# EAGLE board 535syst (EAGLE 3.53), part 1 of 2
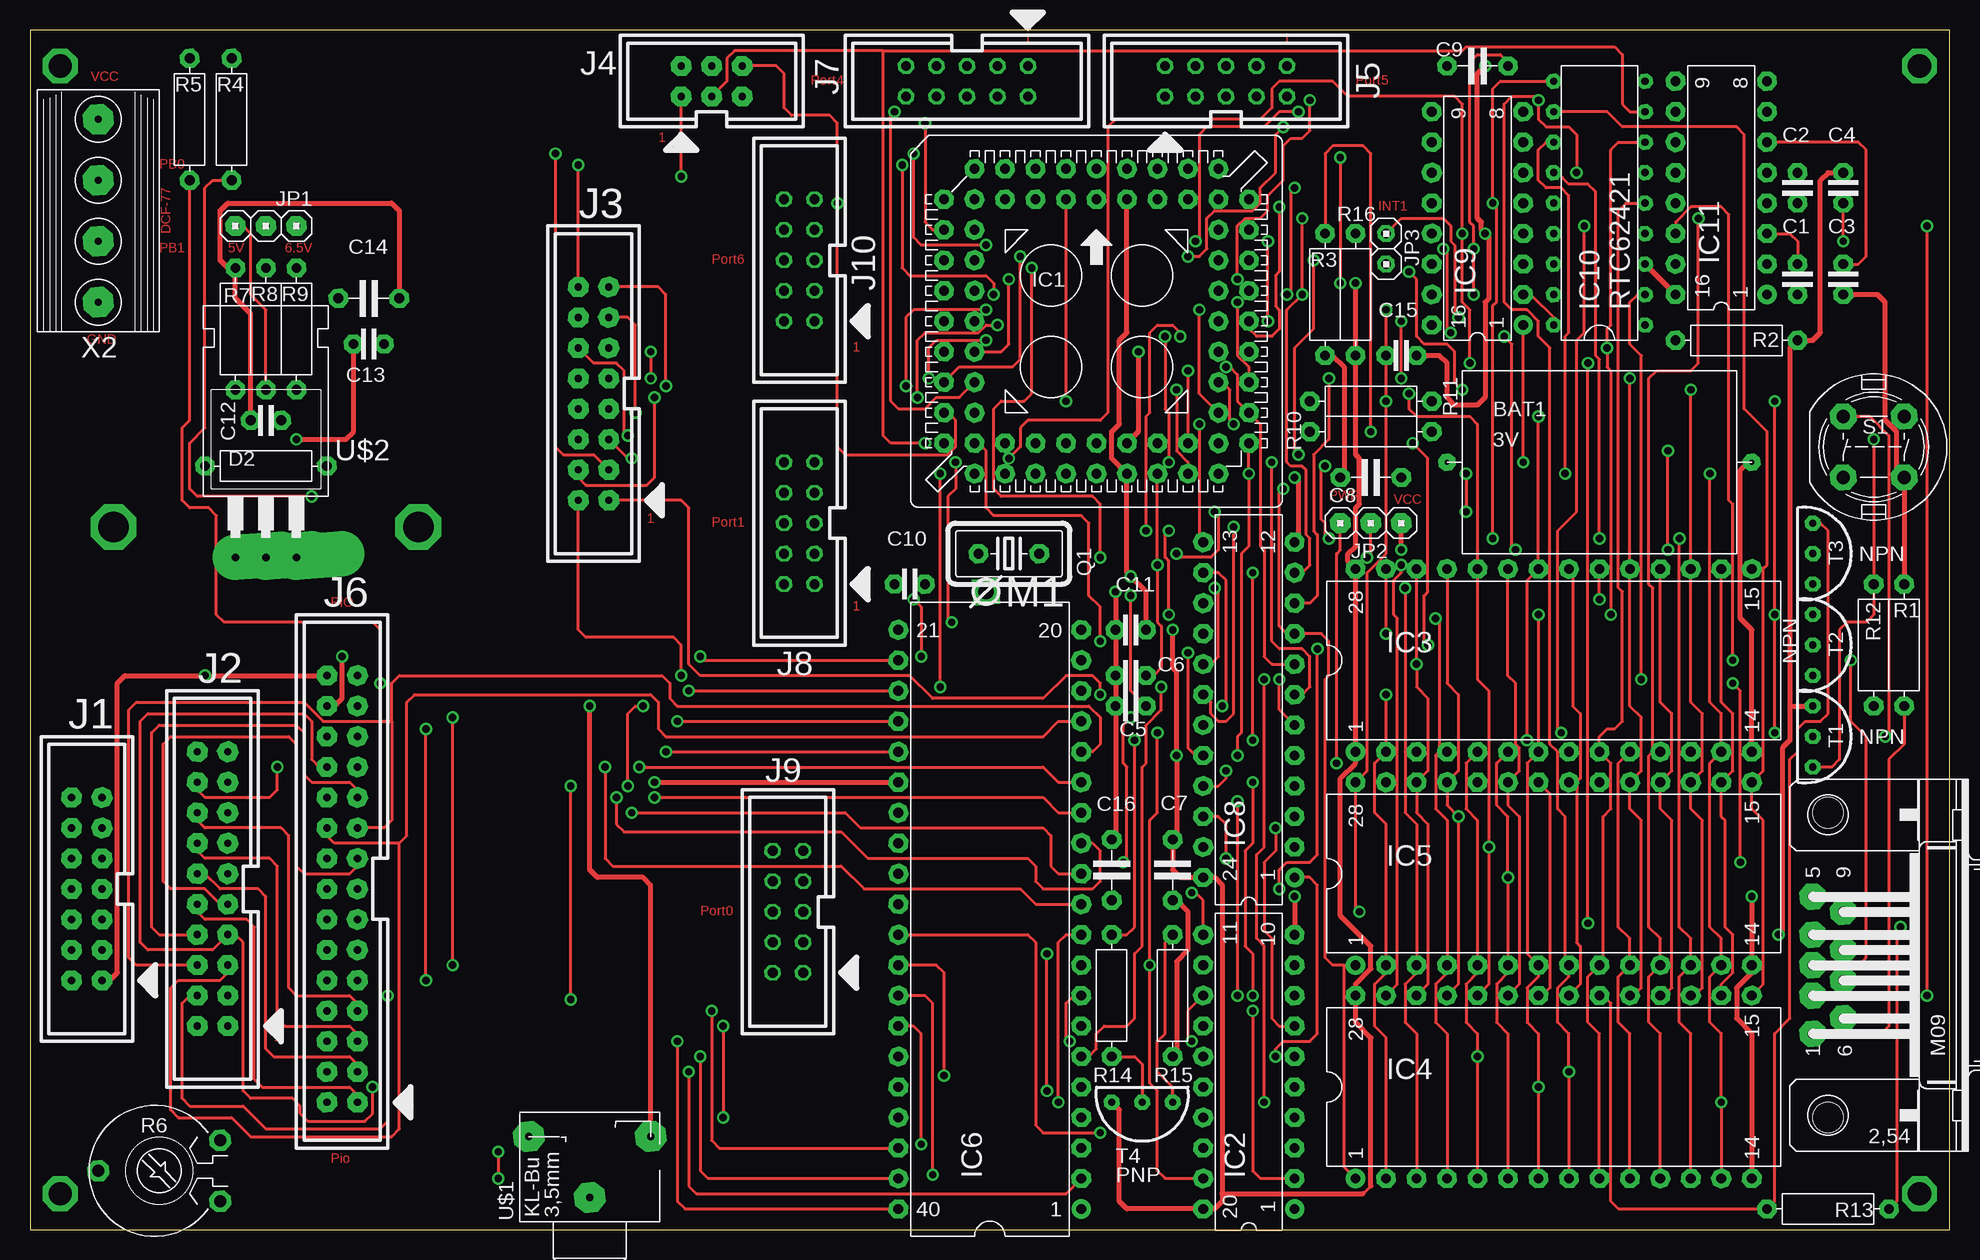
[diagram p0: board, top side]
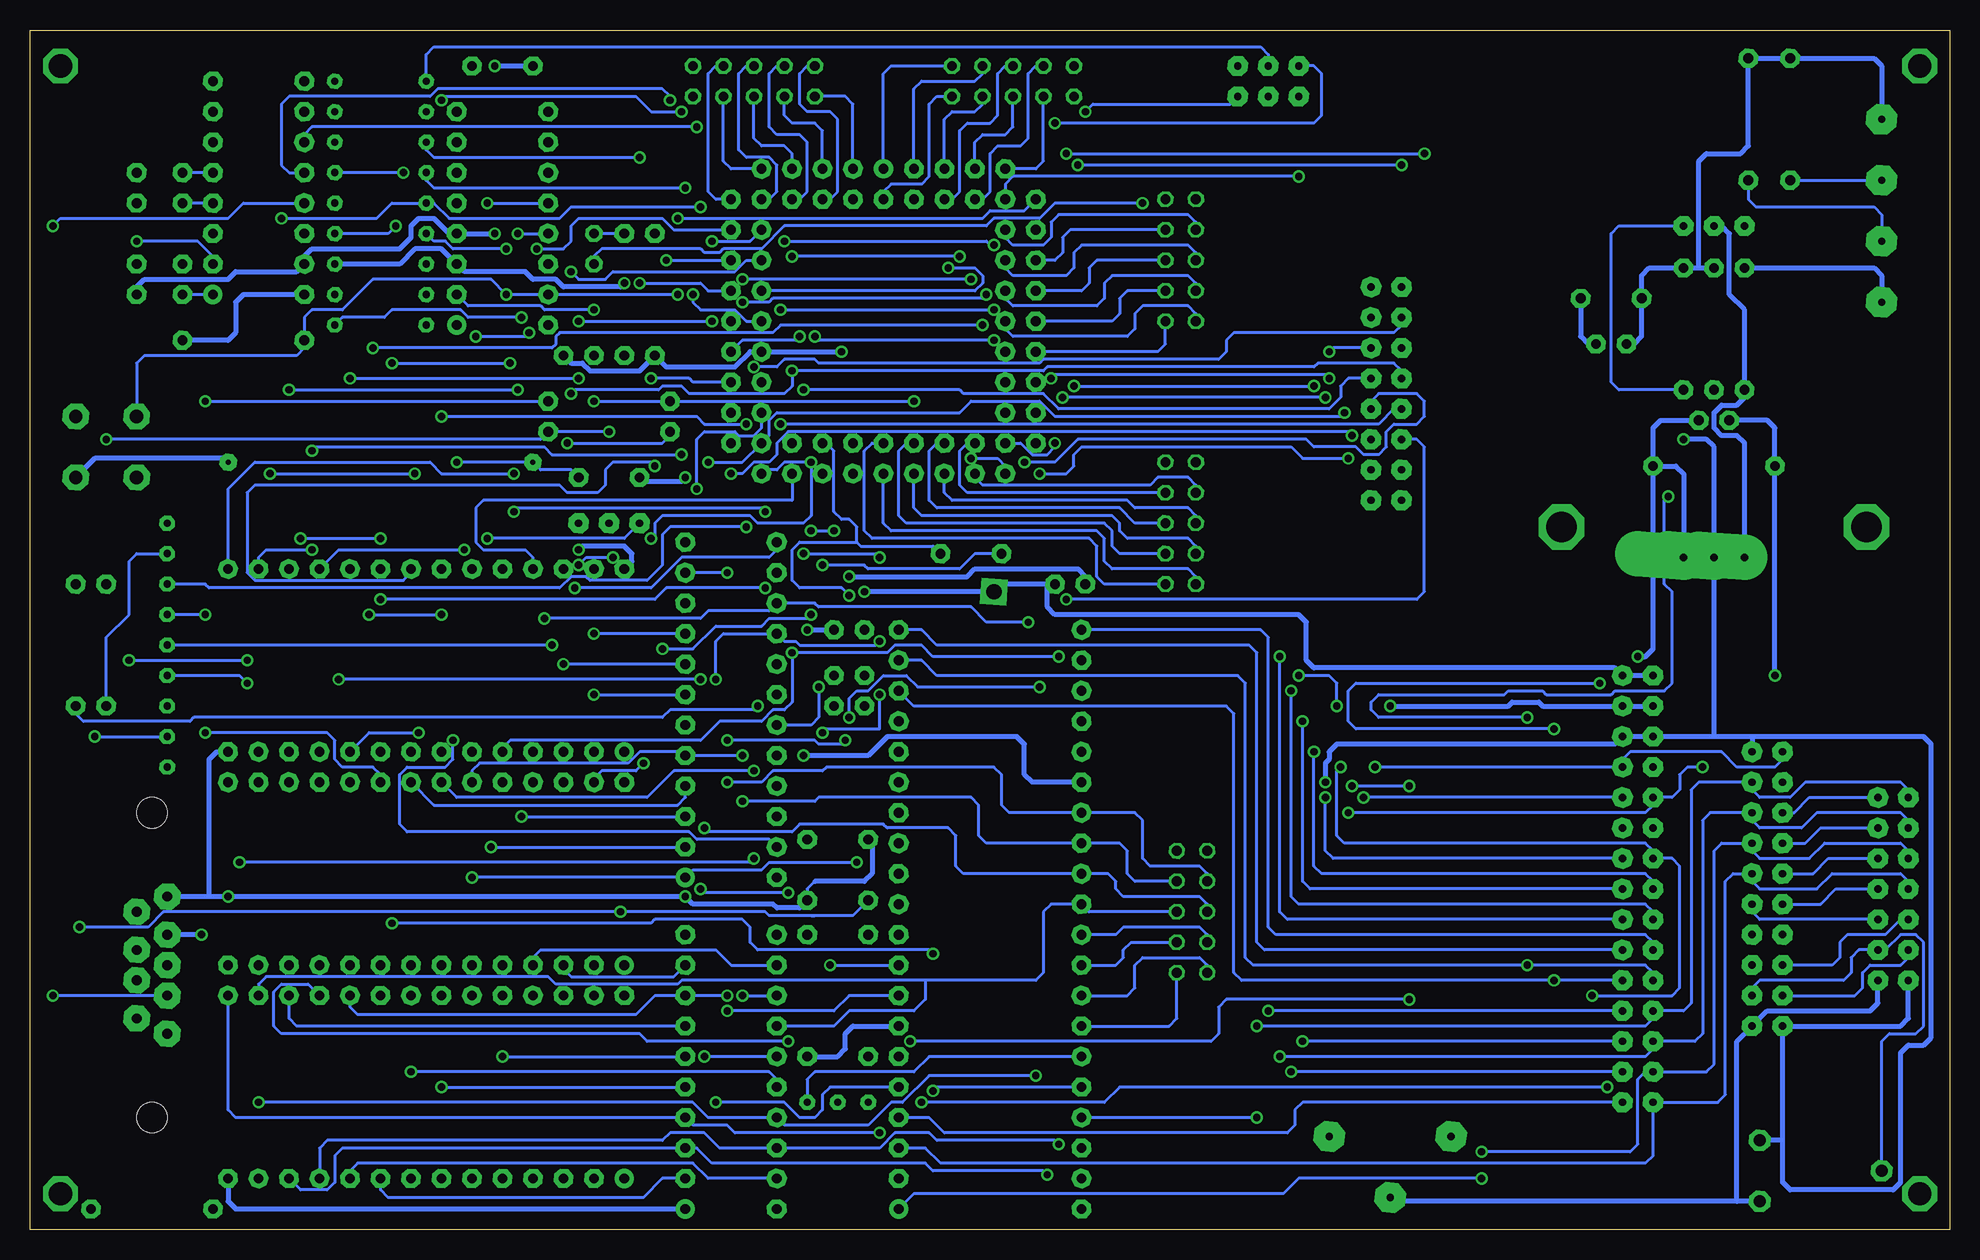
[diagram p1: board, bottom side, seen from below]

Size 159.99 x 99.97 mm. Coordinates in mm from the lower left corner, seen from the top.
Outline: 0,0 159.99,0 159.99,99.97 0,99.97 0,0
Copper layers used: Top, Bottom

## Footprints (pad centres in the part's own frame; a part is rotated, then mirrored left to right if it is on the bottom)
 = drill 0.406 pad 1.422 octagon:  -12.7,0;  12.7,0
2,5 = drill 0.813 pad 1.6 octagon:  -1.27,0;  1.27,0
5 = drill 0.813 pad 1.6 octagon:  -2.54,0;  2.54,0
10 = drill 0.813 pad 1.6 octagon:  -5.08,0;  5.08,0
8 = drill 0.813 pad 1.6 round:  0,12.7 | drill 0.813 pad 1.6 octagon:  0,10.16;  -2.54,12.7;  -2.54,10.16;  -5.08,12.7;  -5.08,10.16;  -7.62,12.7;  -7.62,10.16;  -10.16,12.7;  -12.7,10.16;  -10.16,10.16;  -12.7,7.62;  -10.16,7.62;  -12.7,5.08;  -10.16,5.08;  -12.7,2.54;  -10.16,2.54;  -12.7,0;  -10.16,0;  -12.7,-2.54;  -10.16,-2.54;  -12.7,-5.08;  -10.16,-5.08;  -12.7,-7.62;  -10.16,-7.62;  -12.7,-10.16;  -10.16,-12.7;  -10.16,-10.16;  -7.62,-12.7;  -7.62,-10.16;  -5.08,-12.7;  -5.08,-10.16;  -2.54,-12.7;  -2.54,-10.16;  0,-12.7;  0,-10.16;  2.54,-12.7;  2.54,-10.16;  5.08,-12.7;  5.08,-10.16;  7.62,-12.7;  7.62,-10.16;  10.16,-12.7;  12.7,-10.16;  10.16,-10.16;  12.7,-7.62;  10.16,-7.62;  12.7,-5.08;  10.16,-5.08;  12.7,-2.54;  10.16,-2.54;  12.7,0;  10.16,0;  12.7,2.54;  10.16,2.54;  12.7,5.08;  10.16,5.08;  12.7,7.62;  10.16,7.62;  12.7,10.16;  10.16,12.7;  10.16,10.16;  7.62,12.7;  7.62,10.16;  5.08,12.7;  5.08,10.16;  2.54,12.7;  2.54,10.16
L20 = drill 0.813 pad 1.6 round:  -11.43,-3.81 | drill 0.813 pad 1.6 octagon:  -8.89,-3.81;  -6.35,-3.81;  -3.81,-3.81;  -1.27,-3.81;  1.27,-3.81;  3.81,-3.81;  6.35,-3.81;  8.89,-3.81;  11.43,-3.81;  11.43,3.81;  8.89,3.81;  6.35,3.81;  3.81,3.81;  1.27,3.81;  -1.27,3.81;  -3.81,3.81;  -6.35,3.81;  -8.89,3.81;  -11.43,3.81
L28-6 = drill 0.813 pad 1.6 round:  -16.51,-7.62 | drill 0.813 pad 1.6 octagon:  -13.97,-7.62;  -11.43,-7.62;  -8.89,-7.62;  -6.35,-7.62;  -3.81,-7.62;  -1.27,-7.62;  1.27,-7.62;  3.81,-7.62;  6.35,-7.62;  8.89,-7.62;  11.43,-7.62;  13.97,-7.62;  16.51,-7.62;  16.51,7.62;  13.97,7.62;  11.43,7.62;  8.89,7.62;  6.35,7.62;  3.81,7.62;  1.27,7.62;  -1.27,7.62;  -3.81,7.62;  -6.35,7.62;  -8.89,7.62;  -11.43,7.62;  -13.97,7.62;  -16.51,7.62
L40 = drill 0.813 pad 1.6 round:  -24.13,-7.62 | drill 0.813 pad 1.6 octagon:  -21.59,-7.62;  -19.05,-7.62;  -16.51,-7.62;  -13.97,-7.62;  -11.43,-7.62;  -8.89,-7.62;  -6.35,-7.62;  -3.81,-7.62;  -1.27,-7.62;  1.27,-7.62;  3.81,-7.62;  6.35,-7.62;  8.89,-7.62;  11.43,-7.62;  13.97,-7.62;  16.51,-7.62;  19.05,-7.62;  21.59,-7.62;  24.13,-7.62;  24.13,7.62;  21.59,7.62;  19.05,7.62;  16.51,7.62;  13.97,7.62;  11.43,7.62;  8.89,7.62;  6.35,7.62;  3.81,7.62;  1.27,7.62;  -1.27,7.62;  -3.81,7.62;  -6.35,7.62;  -8.89,7.62;  -11.43,7.62;  -13.97,7.62;  -16.51,7.62;  -19.05,7.62;  -21.59,7.62;  -24.13,7.62
L24-3 = drill 0.813 pad 1.6 round:  -13.97,-3.81 | drill 0.813 pad 1.6 octagon:  -11.43,-3.81;  -8.89,-3.81;  -6.35,-3.81;  -3.81,-3.81;  -1.27,-3.81;  1.27,-3.81;  3.81,-3.81;  6.35,-3.81;  8.89,-3.81;  11.43,-3.81;  13.97,-3.81;  13.97,3.81;  11.43,3.81;  8.89,3.81;  6.35,3.81;  3.81,3.81;  1.27,3.81;  -1.27,3.81;  -3.81,3.81;  -6.35,3.81;  -8.89,3.81;  -11.43,3.81;  -13.97,3.81
L16 = drill 0.813 pad 1.6 round:  -8.89,-3.81 | drill 0.813 pad 1.6 octagon:  -6.35,-3.81;  -3.81,-3.81;  -1.27,-3.81;  1.27,-3.81;  3.81,-3.81;  6.35,-3.81;  8.89,-3.81;  8.89,3.81;  6.35,3.81;  3.81,3.81;  1.27,3.81;  -1.27,3.81;  -3.81,3.81;  -6.35,3.81;  -8.89,3.81
C62421 = drill 0.61 pad 1.27 octagon: 0 10.16,3.81; 1 7.62,3.81; 2 5.08,3.81; 3 2.54,3.81; 4 0,3.81; 5 -2.54,3.81; 6 -5.08,3.81; 7 -7.62,3.81; 8 -10.16,3.81;  -10.16,-3.81;  -7.62,-3.81;  -5.08,-3.81;  -2.54,-3.81;  0,-3.81;  2.54,-3.81;  5.08,-3.81;  7.62,-3.81;  10.16,-3.81
ABA14 = drill 0.61 pad 1.676 octagon:  -7.62,-1.27;  -5.08,-1.27;  -2.54,-1.27;  0,-1.27;  2.54,-1.27;  5.08,-1.27;  7.62,-1.27;  7.62,1.27;  5.08,1.27;  2.54,1.27;  0,1.27;  -2.54,1.27;  -5.08,1.27;  -7.62,1.27
ABA20 = drill 0.61 pad 1.676 octagon:  -11.43,-1.27;  -8.89,-1.27;  -6.35,-1.27;  -3.81,-1.27;  -1.27,-1.27;  -1.27,1.27;  -3.81,1.27;  -6.35,1.27;  -8.89,1.27;  -11.43,1.27;  1.27,1.27;  1.27,-1.27;  3.81,1.27;  3.81,-1.27;  6.35,-1.27;  8.89,-1.27;  11.43,-1.27;  11.43,1.27;  8.89,1.27;  6.35,1.27
ABA16 = drill 0.61 pad 1.676 octagon:  -6.35,-1.27;  -3.81,-1.27;  -1.27,-1.27;  1.27,-1.27;  3.81,-1.27;  6.35,-1.27;  8.89,-1.27;  8.89,1.27;  6.35,1.27;  3.81,1.27;  1.27,1.27;  -1.27,1.27;  -3.81,1.27;  -6.35,1.27;  -8.89,1.27;  -8.89,-1.27
ABA6 = drill 0.61 pad 1.676 octagon:  -2.54,1.27;  0,-1.27;  2.54,-1.27;  2.54,1.27;  0,1.27;  -2.54,-1.27
ABA10 = drill 0.813 pad 1.27 octagon:  -5.08,-1.27;  -2.54,-1.27;  0,-1.27;  2.54,-1.27;  5.08,-1.27;  5.08,1.27;  2.54,1.27;  0,1.27;  -2.54,1.27;  -5.08,1.27
ABA30 = drill 0.61 pad 1.676 octagon:  -17.78,-1.27;  -15.24,-1.27;  -12.7,-1.27;  -10.16,-1.27;  -7.62,-1.27;  -7.62,1.27;  -10.16,1.27;  -12.7,1.27;  -15.24,1.27;  -17.78,1.27;  -5.08,1.27;  -5.08,-1.27;  -2.54,1.27;  -2.54,-1.27;  0,-1.27;  2.54,-1.27;  5.08,-1.27;  5.08,1.27;  2.54,1.27;  0,1.27;  7.62,-1.27;  10.16,-1.27;  12.7,-1.27;  15.24,-1.27;  17.78,-1.27;  17.78,1.27;  15.24,1.27;  12.7,1.27;  10.16,1.27;  7.62,1.27
03 = drill 0.61 pad 1.676 octagon:  -2.54,0;  0,0;  2.54,0
02 = drill 0.813 pad 1.422 octagon:  -1.27,0;  1.27,0
TSTIFT = drill 1.27 pad 2.184 square:  0,0
18U-V = drill 0.813 pad 1.6 octagon:  -2.54,0;  2.54,0
-10 = drill 1.016 pad 1.778 octagon:  -2.54,-5.08;  2.54,-5.08;  0,5.08
6 = drill 1.118 pad 2.159 octagon:  -2.54,2.54;  2.54,2.54;  2.54,-2.54;  -2.54,-2.54
N-PNP = drill 0.61 pad 1.27 octagon:  -2.54,0;  0,0;  2.54,0
INKEN = drill 0.61 pad 2.54 octagon:  -2.54,0;  2.54,-5.08;  2.54,5.08
220H = drill 0.61 pad 3.81 offset:  -2.54,-6.35;  0,-6.35;  2.54,-6.35
NN09 = drill 0.813 pad 2.184 octagon:  -5.715,1.27;  5.715,1.27;  0,1.27;  -2.54,1.27;  2.54,1.27;  -4.445,-1.27;  -1.27,-1.27;  1.27,-1.27;  4.445,-1.27 | hole 2.54: -12.7,0; 12.7,0
AMP-04 = drill 0.61 pad 2.54 octagon:  -7.62,0;  -2.54,0;  2.54,0;  7.62,0

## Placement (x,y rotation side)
BAT1  3V  []  130.78,63.96 0 top
C1  10æ  [2,5]  147.29,79.2 90 top
C2  10æ  [2,5]  147.29,86.82 90 top
C3  10æ  [2,5]  151.1,79.2 90 top
C4  10æ  [2,5]  151.1,86.82 90 top
C5  22p  [2,5]  91.73,43.64 0 top
C6  22p  [2,5]  91.73,46.18 0 top
C7  100nF  [5]  95.22,29.98 270 top
C8  100nF  [5]  111.73,62.69 0 top
C9  100nF  [5]  120.62,96.98 0 top
C10  10æ  [2,5]  73.32,53.8 0 top
C11  680p  [2,5]  91.73,49.99 0 top
C12  10æ  [2,5]  19.66,67.45 180 top
C13  100æ  [2,5]  28.23,73.8 0 top
C14  220n  [5]  28.23,77.61 180 top
C15  10æF  [2,5]  114.27,72.85 0 top
C16  100nF  [5]  90.14,29.98 90 top
D2  1N4007  [10]  19.66,63.64 0 top
IC1  80C535  [8]  88.87,75.7 0 top
IC2  74373  [L20]  101.57,13.16 90 top
IC3  27C256  [L28-6]  126.97,47.45 0 top
IC4  28C256  [L28-6]  126.97,11.89 0 top
IC5  62256  [L28-6]  126.97,29.67 0 top
IC6  82C55A  [L40]  79.98,25.86 90 top
IC8  5C060  [L24-3]  101.57,43.32 90 top
IC9  MAX693  [L16]  120.62,84.28 90 top
IC10  RTC62421  [C62421]  130.78,85.55 90 top
IC11  MAX232  [L16]  140.94,86.82 90 top
J1  FLABA14  [ABA14]  4.74,28.4 270 top
J2  FLABA20  [ABA20]  15.21,28.4 270 top
J3  FLABA16  [ABA16]  46.96,69.67 270 top
J4  FLABA6  [ABA6]  56.81,95.71 180 top
J5  FLABA10  [ABA10]  99.67,95.71 0 top
J6  FLABA30  [ABA30]  26.01,28.4 270 top
J7  FLABA10  [ABA10]  78.08,95.71 180 top
J8  FLABA10  [ABA10]  64.11,58.88 90 top
J9  FLABA10  [ABA10]  63.16,26.49 90 top
J10  FLABA10  [ABA10]  64.11,80.78 90 top
JP1  CON03X1  [03]  19.66,83.64 180 top
JP2  CON03X1  [03]  111.73,58.88 0 top
JP3  CON02X1  [02]  113,81.74 90 top
M1  LTSTIFT  [TSTIFT]  79.67,53.16 0 top
Q1  12MHz  [18U-V]  81.57,56.34 0 top
R1  10k  [10]  156.18,48.72 90 top
R2  1k  [10]  142.21,74.12 0 top
R3  4k7  [10]  107.92,77.93 90 top
R4  10k  [10]  16.8,92.53 90 top
R5  10k  [10]  13.31,92.53 90 top
R6  10k  [-10]  10.77,4.9 90 top
R7  470R  [10]  17.12,75.07 270 top
R8  150R  [10]  19.66,75.07 90 top
R9  100R  [10]  22.2,75.07 90 top
R10  4k7  [10]  111.73,66.5 0 top
R11  10k  [10]  111.73,69.04 0 top
R12  4k7  [10]  153.64,48.72 90 top
R13  10k  [10]  149.83,1.73 180 top
R14  4k7  [10]  90.14,19.51 90 top
R15  1k  [10]  95.22,19.51 90 top
R16  4k7  [10]  110.46,77.93 90 top
S1  DT6  [6]  153.64,65.23 0 top
T1  NPN  [N-PNP]  148.56,41.1 90 top
T2  NPN  [N-PNP]  148.56,48.72 90 top
T3  NPN  [N-PNP]  148.56,56.34 90 top
T4  PNP  [N-PNP]  92.68,10.62 0 top
U$1  KLINKEN  [INKEN]  46.65,5.22 90 top
U$2  LM317  [220H]  19.66,62.37 0 top
X1  9 pol  [NN09]  149.83,22.05 90 top
X2  DCF  [AMP-04]  5.69,84.91 270 top

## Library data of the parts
BAT1 = BATTERY
C1-C16 D2 R1-R16 = DISCRETE
IC1 = INTEL
IC2 = 74XX
IC3 IC4 = MEMNEC
IC5 = MEMHITCH
IC6 = HARRIS
IC8 = PAL
IC9 IC11 = MAXIM
IC10 = Clock
J1-J10 JP1-JP3 M1 X2 = CONNECT
Q1 = QUARTZ
S1 = KEY
T1-T4 U$2 = LINEAR
U$1 = HIRSCHM
X1 = SUBD-A

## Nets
+12V: C12. D2. J6. U$1. U$2.
A0: IC2. IC3. IC4. IC5. IC6. IC10. J3.
A1: IC2. IC3. IC4. IC5. IC6. IC10. J3.
A2: IC2. IC3. IC4. IC5. IC10. J3.
A3: IC2. IC3. IC4. IC5. IC10. J3.
A4: IC2. IC3. IC4. IC5. IC8. J3.
A5: IC2. IC3. IC4. IC5. IC8. J3.
A6: IC2. IC3. IC4. IC5. IC8. J3.
A7: IC2. IC3. IC4. IC5. IC8. J3.
A8: IC1. IC3. IC4. IC5. IC8. J3.
A9: IC1. IC3. IC4. IC5. IC8. J3.
A10: IC1. IC3. IC4. IC5. IC8. J3.
A11: IC1. IC3. IC4. IC5. IC8. J3.
A12: IC1. IC3. IC4. IC5. IC8. J3.
A13: IC1. IC3. IC4. IC5. IC8. J3.
A14: IC1. IC3. IC4. IC5. IC8. J3.
A15: IC1. IC8. J3.
ALE: IC1. IC2.
CS_E^2: IC8. T3.
CS_PIO: IC6. IC8.
CS_PROM: IC3. IC8.
CS_RAM: IC8. T2.
CS_RTC: IC8. IC10.
GND: BAT1. C3. C5. C6. C7. C8. C9. C10. C11. C12. C13. C14. C15. C16. D2. IC1. IC2. IC3. IC4. IC5. IC6. IC8. IC9. IC11. J1. J2. J6. M1. R1. R3. R6. R7. R15. S1. U$1. X1. X2.
INT0: IC1. J4.
INT1: IC1. J4. JP3.
MODE: IC8. R1. X1.
N$1: BAT1. C8. IC9.
N$2: R3. R10. R12. T1.
N$3: R12. T3.
N$4: R10. T2.
N$5: IC4. R13. T3.
N$6: IC5. R11. T2.
N$7: C4. IC11.
N$8: C3. IC11.
N$9: IC6. R15. T4.
N$10: JP1. R7. U$2.
N$11: C1. IC11.
N$12: C1. IC11.
N$13: C2. IC11.
N$14: C2. IC11.
N$15: IC11. X1.
N$16: IC11. X1.
N$17: J1. J2. R6.
N$18: R14. T4.
N$19: IC10. JP3. R16.
N$21: IC4. JP2.
N$23: JP1. R8.
N$24: JP1. R9.
N$34: C5. IC1. Q1.
N$35: C6. IC1. Q1.
P00: IC1. IC2. IC3. IC4. IC5. IC6. IC10.4 J9.
P01: IC1. IC2. IC3. IC4. IC5. IC6. IC10.3 J9.
P02: IC1. IC2. IC3. IC4. IC5. IC6. IC10.2 J9.
P03: IC1. IC2. IC3. IC4. IC5. IC6. IC10.1 J9.
P04: IC1. IC2. IC3. IC4. IC5. IC6. J9.
P05: IC1. IC2. IC3. IC4. IC5. IC6. J9.
P06: IC1. IC2. IC3. IC4. IC5. IC6. J9.
P07: IC1. IC2. IC3. IC4. IC5. IC6. J9.
P10: IC1. J8.
P11: IC1. J8.
P12: IC1. J8.
P13: IC1. J8.
P14: IC1. J8.
P15: IC1. J8.
P16: IC1. J8.
P17: IC1. J8.
P40: IC1. J7.
P41: IC1. J7.
P42: IC1. J7.
P43: IC1. J7.
P44: IC1. J7.
P45: IC1. J7.
P46: IC1. J7.
P47: IC1. J7.
P50: IC1. J5.
P51: IC1. J5.
P52: IC1. J5.
P53: IC1. J5.
P54: IC1. J5.
P55: IC1. J5.
P56: IC1. J5.
P57: IC1. J5.
P60: IC1. J10.
P61: IC1. J10.
P62: IC1. J10.
P63: IC1. J10.
P64: IC1. J10.
P65: IC1. J10.
P66: IC1. J10.
P67: IC1. J10.
PA0: IC6. J1. J2. J6.
PA1: IC6. J1. J2. J6.
PA2: IC6. J1. J2. J6.
PA3: IC6. J1. J2. J6.
PA4: IC6. J1. J2. J6.
PA5: IC6. J1. J2. J6.
PA6: IC6. J1. J2. J6.
PA7: IC6. J1. J2. J6.
PB0: IC6. J6. R5. X2.
PB1: IC6. J6. R4. X2.
PB2: IC6. J6.
PB3: IC6. J6.
PB4: IC6. J6.
PB5: IC6. J6.
PB6: IC6. J6.
PB7: IC6. J6.
PC0: IC6. J1. J2. J6.
PC1: IC6. J1. J2. J6.
PC2: IC6. J1. J2. J6.
PC3: IC6. J2. J6.
PC4: IC6. J2. J6.
PC5: IC6. J2. J6.
PC6: IC6. J2. J6.
PC7: IC6. J2. J6.
PSEN: IC1. IC3. IC8.
PWR: IC5. IC9. IC10.0 J4. JP2.
RD: IC1. IC6. IC8. IC10. J4.
RESET: C9. IC1. IC8. IC9. IC10.5 R2. R14. S1. T1.
RXD: IC1. IC11.
TXD: IC1. IC11.
VAGND: IC1. J4.
VAREF: IC1. J4.
VCC: C4. C7. C10. C11. C13. C14. IC1. IC2. IC3. IC4. IC6. IC8. IC9. IC10. IC11. J1. J2. J6. JP2. R2. R4. R5. R6. R8. R9. R16. T1. T4. U$2. X1. X2.
VN: IC4. IC5. IC8.
VPD: C15. C16. IC1. IC5. IC9. IC10.8 R11. R13.
WR: IC1. IC6. IC9.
